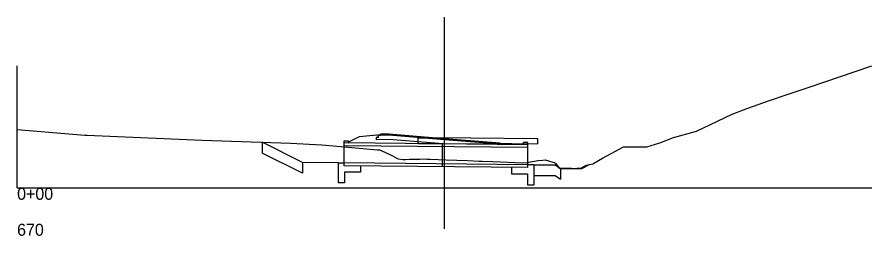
# Model space of a CAD drawing. Extents: x 157201 to 163282, y 424960 to 427200.
# Drawn here: x 163081.9 to 163281.9, y 425960.5 to 426011.6 of the extents above; entities that cross this region are included whole.
import ezdxf

# ---------------------------------------------------------------- set-up
doc = ezdxf.new("R2010")
doc.units = 0
for name, color, linetype in [('BD_X_Building', 7, 'Continuous'), ('DR_X_Elev_Flow', 7, 'Continuous'), ('SV_X_Text', 7, 'Continuous'), ('UT_X_Electric_Cells', 7, 'Continuous'), ('UT_X_Sanitary_Cells', 7, 'Continuous'), ('UT_X_Telecom_Cells', 7, 'Continuous'), ('UT_X_Water_Cells', 7, 'Continuous'), ('VG_X_Cells', 7, 'Continuous')]:
    doc.layers.add(name, color=color, linetype=linetype)

msp = doc.modelspace()

# ---------------------------------------------------------------- linework, layer by layer
at = {"layer": 'BD_X_Building'}
for p, q in [((163148.66, 425977.65), (163139.21, 425982.37)), ((163139.21, 425982.37), (163139.21, 425979.87)), ((163148.66, 425975.15), (163139.21, 425979.87)), ((163148.66, 425977.65), (163148.66, 425975.15)), ((163202.78, 425977.13), (163207.78, 425977.08)), ((163207.78, 425977.08), (163208.98, 425976.28)), ((163208.98, 425976.28), (163208.98, 425973.78)), ((163202.78, 425974.63), (163207.78, 425974.58)), ((163207.78, 425974.58), (163208.98, 425973.78))]:
    msp.add_line(p, q, dxfattribs=at)
at = {"layer": 'DR_X_Elev_Flow'}
for p, q in [((163175.73, 425982.1), (163175.73, 425983.35)), ((163175.73, 425982.1), (163203.7, 425981.98)), ((163188, 425983.41), (163203.7, 425983.24)), ((163203.7, 425981.98), (163203.7, 425983.24))]:
    msp.add_line(p, q, dxfattribs=at)
msp.add_lwpolyline([(163188, 425983.41), (163178.27, 425983.36), (163175.73, 425983.35)], dxfattribs=at)
at = {"layer": 'SV_X_Text'}
for q in [(163081.87, 426000.25), (163281.87, 425971.74)]:
    msp.add_line((163081.87, 425971.74), q, dxfattribs=at)
at = {"layer": 'UT_X_Electric_Cells'}
msp.add_line((163181.87, 425962.15), (163181.87, 426011.63), dxfattribs=at)
at = {"layer": 'UT_X_Sanitary_Cells'}
for p, q in [((163158.37, 425982.23), (163158.37, 425982.73)), ((163158.37, 425982.73), (163159.37, 425982.73)), ((163201.37, 425981.8), (163158.37, 425982.23)), ((163158.37, 425976.9), (163158.37, 425982.23)), ((163159.37, 425982.22), (163159.37, 425982.73)), ((163200.37, 425981.81), (163200.37, 425982.3)), ((163201.37, 425982.3), (163200.37, 425982.3)), ((163201.37, 425981.8), (163201.37, 425982.3)), ((163201.37, 425981.13), (163158.37, 425981.56)), ((163181.37, 425976.67), (163181.37, 425982)), ((163201.37, 425976.47), (163201.37, 425981.8)), ((163156.95, 425977.56), (163158.37, 425977.56)), ((163156.95, 425977.56), (163156.95, 425972.9)), ((163201.37, 425977.13), (163158.37, 425977.56)), ((163201.37, 425976.47), (163158.37, 425976.9)), ((163162.2, 425976.86), (163162.2, 425975.4)), ((163197.53, 425976.5), (163197.53, 425974.97)), ((163202.78, 425977.13), (163201.37, 425977.13)), ((163202.78, 425977.13), (163202.78, 425972.47)), ((163162.2, 425975.4), (163158.45, 425975.4)), ((163158.45, 425975.4), (163158.45, 425972.9)), ((163197.53, 425974.97), (163201.28, 425974.97)), ((163201.28, 425974.97), (163201.28, 425972.47)), ((163158.45, 425972.9), (163156.95, 425972.9)), ((163201.28, 425972.47), (163202.78, 425972.47))]:
    msp.add_line(p, q, dxfattribs=at)
at = {"layer": 'UT_X_Telecom_Cells'}
for p, q in [((163166.87, 425984.12), (163161.87, 425983.62)), ((163161.87, 425983.62), (163159.37, 425982.37)), ((163156.95, 425977.56), (163148.66, 425977.65)), ((163208.98, 425976.28), (163213.98, 425976.28)), ((163213.98, 425976.28), (163215.77, 425977.18))]:
    msp.add_line(p, q, dxfattribs=at)
at = {"layer": 'UT_X_Water_Cells'}
msp.add_lwpolyline([(163081.87, 425985.33), (163094.91, 425984.28), (163097.72, 425984.07), (163098.29, 425984.04), (163100, 425983.96), (163125.13, 425982.85), (163145.83, 425982.14), (163153.15, 425981.81), (163160.17, 425981.16), (163166.16, 425980.63), (163166.64, 425980.58), (163166.68, 425980.58), (163166.8, 425980.52), (163167.04, 425980.42), (163169.26, 425979.41), (163171.04, 425978.53), (163172.19, 425978.39), (163172.5, 425978.39), (163172.76, 425978.39), (163173.69, 425978.4), (163175.03, 425978.45), (163175.37, 425978.43), (163176.08, 425978.47), (163177.66, 425978.48), (163177.87, 425978.46), (163178.51, 425978.41), (163182.28, 425978.3), (163187.25, 425978.1), (163189.99, 425977.99), (163190.71, 425977.97), (163193.16, 425977.85), (163200.1, 425977.55), (163201.11, 425977.63), (163203.81, 425978.15), (163204.86, 425978.22), (163205.44, 425978.26), (163207.23, 425977.76), (163207.5, 425977.64), (163207.8, 425977.51), (163207.85, 425977.51), (163208.69, 425976.36), (163211.55, 425976.31), (163212.64, 425976.28), (163212.88, 425976.31), (163213.8, 425976.34), (163214.76, 425976.89), (163215.05, 425977.07), (163216.58, 425977.31), (163218.81, 425978.63), (163223.78, 425981.35), (163227.5, 425981.34), (163229.17, 425981.34), (163232.21, 425982.23), (163235.47, 425983.47), (163240.8, 425985.01), (163245.76, 425987.32), (163249.17, 425988.97), (163252.86, 425990.32), (163257.66, 425992.1), (163262.24, 425993.66), (163266.99, 425995.17), (163281.87, 426000.24)], dxfattribs=at)
at = {"layer": 'VG_X_Cells'}
for p, q in [((163168.87, 425984.26), (163166.87, 425984.24)), ((163166.87, 425984.24), (163166.87, 425983.99)), ((163168.87, 425984.01), (163166.87, 425983.99)), ((163181.87, 425983.22), (163168.87, 425984.26)), ((163181.87, 425982.97), (163168.87, 425984.01)), ((163166.37, 425983.49), (163165.87, 425983.48)), ((163165.87, 425983.48), (163165.87, 425982.98)), ((163168.87, 425983.01), (163165.87, 425982.98)), ((163166.87, 425983.99), (163166.37, 425983.99)), ((163166.37, 425983.99), (163166.37, 425983.49)), ((163181.55, 425982), (163168.87, 425983.01)), ((163194.87, 425982.18), (163181.87, 425983.22)), ((163194.87, 425981.93), (163181.87, 425982.97)), ((163194.87, 425982.18), (163194.87, 425981.93)), ((163194.87, 425982.18), (163200.37, 425982.05)), ((163195.37, 425981.89), (163194.87, 425981.93)), ((163195.37, 425981.89), (163195.37, 425981.86))]:
    msp.add_line(p, q, dxfattribs=at)

# ---------------------------------------------------------------- texts
at = {"layer": 'SV_X_Text'}
for s, p in [('0+00', (163081.87, 425968.94)), ('670', (163081.87, 425960.54))]:
    msp.add_text(s, height=2.8, dxfattribs=at).set_placement(p)

doc.saveas('drawing.dxf')
